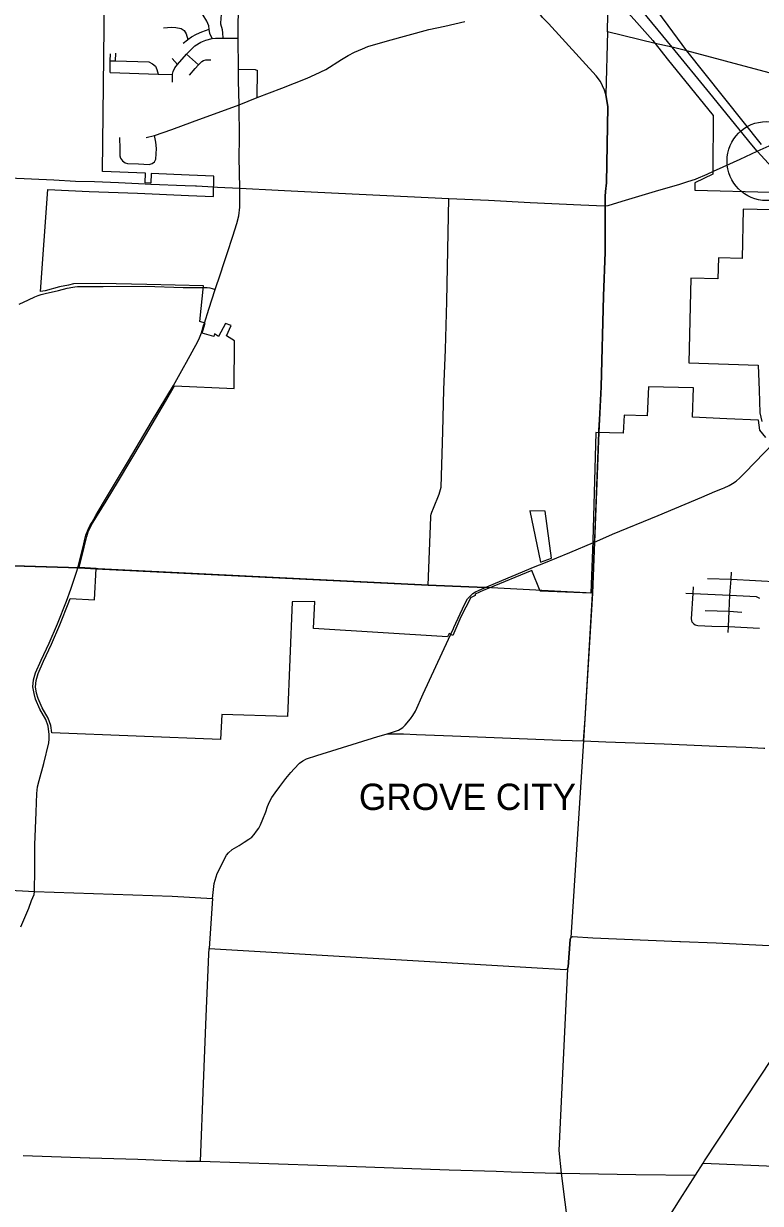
# Model space of a CAD drawing. Extents: x 1659811 to 1934326, y 644115 to 934867.
# Drawn here: x 1783780 to 1797773, y 677476 to 699875 of the extents above; entities that cross this region are included whole.
import ezdxf

# ---------------------------------------------------------------- set-up
doc = ezdxf.new("R2010")
doc.units = 0
for name, color, linetype in [('Default', 7, 'Continuous'), ('GM_X_City_Street', 7, 'Continuous'), ('GM_X_Corporation', 7, 'Continuous'), ('GM_X_Corporation_Text', 7, 'Continuous'), ('GM_X_County_Road', 7, 'Continuous'), ('GM_X_Interstate_Route', 7, 'Continuous'), ('GM_X_Township', 7, 'Continuous'), ('GM_X_Township_Road', 7, 'Continuous'), ('GM_X_US_Route', 7, 'Continuous')]:
    doc.layers.add(name, color=color, linetype=linetype)

msp = doc.modelspace()

# ---------------------------------------------------------------- linework, layer by layer
at = {"layer": 'Default'}
msp.add_circle((1797890, 697266), 750, dxfattribs=at)
at = {"layer": 'GM_X_City_Street'}
for points in [[(1787860, 699018), (1787858, 699597), (1787860, 700358), (1787857, 700738), (1787852, 701242), (1787854, 701665), (1787855, 702336), (1787857, 703006), (1787855, 703286)], [(1787568, 699600), (1787565, 699703), (1787558, 699757), (1787529, 699867), (1787526, 699907), (1787530, 699946), (1787540, 700071), (1787544, 700150), (1787537, 700203), (1787516, 700260), (1787490, 700314), (1787410, 700486), (1787371, 700689)], [(1787359, 699591), (1787316, 699688), (1787305, 699768), (1787296, 699835), (1787257, 699924), (1787193, 700037), (1787087, 700199), (1786996, 700308), (1786904, 700363)], [(1794824, 696413), (1794825, 696594), (1794834, 696685), (1794851, 696855), (1794873, 698294), (1794837, 698528), (1794811, 698613), (1794734, 698773), (1794654, 698882), (1793750, 699877), (1793637, 699992), (1793560, 700096), (1793541, 700135), (1793499, 700228), (1793486, 700349)], [(1786436, 699794), (1786590, 699806), (1786672, 699801), (1786772, 699784), (1786828, 699747), (1786867, 699684), (1786902, 699576)], [(1786813, 699503), (1786890, 699568), (1786902, 699576), (1786972, 699621), (1787067, 699672), (1787164, 699720), (1787305, 699768)], [(1787874, 698335), (1788217, 698471), (1788682, 698648), (1789167, 698839), (1789320, 698907), (1789523, 699005), (1789815, 699194), (1789942, 699267), (1790064, 699333), (1790216, 699398), (1790319, 699438), (1790694, 699548), (1791479, 699763), (1791782, 699829), (1792162, 699917)], [(1786606, 698762), (1786608, 698906), (1786608, 698916), (1786623, 698964), (1786650, 699034), (1786706, 699100), (1786875, 699296), (1786878, 699299), (1787035, 699454), (1787143, 699521), (1787241, 699558), (1787359, 699591), (1787427, 699599), (1787568, 699600), (1787858, 699597)], [(1785525, 699166), (1785529, 699315)], [(1785424, 698946), (1785425, 699168), (1785432, 699299)], [(1785425, 699168), (1785525, 699166), (1786160, 699148), (1786228, 699113), (1786284, 699069), (1786311, 699004), (1786334, 698915)], [(1786602, 699211), (1786706, 699100)], [(1786875, 699296), (1787102, 699091)], [(1786932, 698898), (1787036, 699025), (1787102, 699091), (1787164, 699155), (1787197, 699177), (1787241, 699190), (1787265, 699190), (1787333, 699187)], [(1785424, 698946), (1786334, 698915), (1786608, 698906)], [(1787874, 698334), (1787874, 698335), (1787863, 698796), (1787860, 699008), (1787860, 699018)], [(1787860, 699008), (1788180, 699002), (1788221, 698982)], [(1788217, 698471), (1788221, 698982)], [(1786109, 697716), (1786264, 697748), (1786593, 697867), (1786985, 698008), (1787874, 698335)], [(1787878, 697701), (1787874, 698334)], [(1785601, 697716), (1785608, 697498), (1785608, 697405), (1785608, 697365), (1785620, 697318), (1785657, 697268), (1785707, 697231), (1785753, 697219), (1785960, 697210), (1786164, 697200), (1786225, 697219), (1786264, 697254), (1786292, 697299), (1786302, 697505), (1786292, 697627), (1786264, 697748)], [(1787886, 696753), (1787886, 696753), (1787877, 697338), (1787878, 697696), (1787878, 697701)], [(1796541, 696924), (1796553, 696928), (1796764, 697018), (1796881, 697072)], [(1794815, 696413), (1794824, 696413), (1794882, 696423), (1795150, 696503), (1795462, 696597), (1795846, 696710), (1796227, 696823), (1796396, 696877), (1796541, 696924)], [(1787465, 696773), (1787886, 696753)], [(1787581, 695318), (1787644, 695510), (1787755, 695837), (1787831, 696083), (1787865, 696227), (1787884, 696389), (1787886, 696506), (1787886, 696753)], [(1787886, 696753), (1788614, 696715), (1788733, 696708)], [(1788733, 696708), (1789370, 696675), (1791855, 696557), (1792612, 696521), (1793399, 696481), (1794364, 696432), (1794815, 696413)], [(1791515, 690529), (1791520, 690559), (1791534, 690600), (1791565, 690676), (1791675, 690939), (1791710, 691076), (1791741, 692131), (1791760, 692924), (1791791, 693686), (1791820, 694601), (1791855, 696557)], [(1794723, 692465), (1794750, 692977), (1794796, 694700), (1794822, 695537), (1794824, 696413)], [(1787206, 694162), (1787215, 694190), (1787299, 694452), (1787421, 694829), (1787518, 695126), (1787581, 695318)], [(1787268, 694866), (1787316, 694859), (1787360, 694848), (1787421, 694829)], [(1794627, 690096), (1794704, 692111), (1794706, 692149)], [(1794896, 690150), (1794967, 690182), (1795830, 690539), (1796659, 690885), (1796910, 690990), (1797053, 691047)], [(1791461, 689213), (1791511, 690507), (1791515, 690529)], [(1792546, 689167), (1792624, 689200), (1793496, 689565), (1793662, 689634), (1794151, 689836), (1794604, 690023)], [(1785153, 689525), (1789400, 689315)], [(1797159, 688314), (1797165, 688429), (1797177, 688723), (1797191, 689023), (1797219, 689325), (1797223, 689459)], [(1789400, 689315), (1791461, 689213), (1792546, 689167)], [(1796770, 689338), (1797219, 689325), (1798139, 689277)], [(1791954, 688409), (1792155, 688846), (1792210, 688952), (1792312, 689056), (1792364, 689086), (1792418, 689112), (1792546, 689167)], [(1796354, 689062), (1796496, 689056), (1797191, 689023), (1797575, 689007), (1797690, 688999), (1797755, 688969)], [(1796508, 688481), (1796480, 688509), (1796467, 688576), (1796496, 689056), (1796504, 689184)], [(1796725, 688731), (1797177, 688723)], [(1797177, 688723), (1797422, 688704)], [(1796508, 688481), (1796535, 688458), (1796583, 688449), (1796849, 688438), (1797165, 688429), (1797753, 688400)], [(1794416, 686257), (1794442, 686678)], [(1793981, 686274), (1794416, 686257)], [(1794416, 686257), (1794416, 686257), (1794840, 686242)], [(1796257, 682451), (1796936, 682422), (1798693, 682335), (1798738, 682332)]]:
    msp.add_lwpolyline(points, dxfattribs=at)
at = {"layer": 'GM_X_Corporation'}
for points in [[(1797878, 692016), (1797761, 692155), (1797739, 692347), (1797135, 692373), (1796483, 692401), (1796502, 692961), (1795648, 692976), (1795623, 692428), (1795183, 692443), (1795165, 692098), (1794646, 692113), (1794591, 690057), (1794554, 689062), (1793588, 689102), (1793430, 689495), (1792602, 689150), (1792522, 689120), (1792355, 689043), (1792357, 689019), (1792282, 688977), (1792273, 688982), (1792085, 688610), (1791929, 688257), (1791865, 688297), (1791829, 688232), (1789283, 688392), (1789311, 688902), (1788878, 688896), (1788791, 686723), (1787546, 686758), (1787521, 686284), (1784315, 686409), (1784297, 686550), (1784248, 686686), (1784135, 686884), (1784054, 687065), (1784026, 687166), (1784005, 687285), (1784016, 687404), (1784055, 687534), (1784161, 687771), (1784313, 688095), (1784468, 688460), (1784642, 688892), (1784665, 688961), (1785129, 688938), (1785159, 689533), (1784834, 689548), (1784931, 689934), (1784982, 690138), (1785006, 690224), (1785068, 690356), (1785346, 690811), (1785585, 691197), (1786031, 691948), (1786472, 692703), (1786647, 692995), (1787777, 692949), (1787788, 693850), (1787631, 693946), (1787720, 694143), (1787615, 694183), (1787480, 693935), (1787407, 693985), (1787393, 693937), (1787173, 694001), (1787192, 694061), (1787229, 694190), (1787130, 694219), (1787197, 694898), (1786123, 694919), (1785249, 694942), (1784729, 694937), (1784634, 694912), (1784460, 694879), (1784187, 694804), (1784101, 694787), (1784238, 696723), (1785023, 696690), (1785946, 696653), (1786913, 696612), (1787386, 696593), (1787395, 696979), (1786927, 696998), (1786206, 697031), (1786198, 696846), (1786090, 696851), (1786098, 697036), (1785281, 697066), (1785330, 701438)], [(1797796, 697579), (1796374, 699359), (1795561, 700471)], [(1795016, 700366), (1795730, 699557), (1795774, 699500), (1796002, 699205), (1796875, 698131), (1796869, 697090), (1796869, 697014), (1796529, 696855), (1796530, 696713), (1797967, 696678)], [(1798248, 696334), (1797448, 696353), (1797426, 695417), (1796976, 695428), (1796966, 695028), (1796454, 695040), (1796416, 693437), (1797732, 693391), (1797750, 692915), (1797765, 692483), (1797798, 692324)]]:
    msp.add_lwpolyline(points, dxfattribs=at)
msp.add_lwpolyline([(1793596, 689653), (1793803, 689728), (1793686, 690619), (1793395, 690626)], close=True, dxfattribs=at)
at = {"layer": 'GM_X_County_Road'}
for points in [[(1797603, 697403), (1797710, 697452), (1797940, 697557), (1798111, 697632), (1798183, 697665)], [(1796881, 697072), (1797064, 697155), (1797387, 697304), (1797603, 697403)], [(1782535, 694298), (1782550, 695153), (1782591, 696469), (1782608, 696832), (1782612, 696920), (1782619, 696976), (1783507, 696946), (1784356, 696907), (1784769, 696885), (1785129, 696875), (1785584, 696857), (1786091, 696836), (1786195, 696829), (1786848, 696802), (1787044, 696794)], [(1787044, 696794), (1787062, 696793), (1787389, 696777), (1787465, 696773)], [(1783695, 694551), (1783871, 694632), (1783993, 694688), (1784059, 694711), (1784115, 694732), (1784191, 694752), (1784440, 694810), (1784605, 694851), (1784718, 694873), (1784755, 694880), (1784804, 694882), (1784877, 694883), (1785289, 694884), (1786094, 694888), (1786813, 694868), (1787193, 694865), (1787264, 694866), (1787268, 694866)], [(1786873, 693447), (1787091, 693837), (1787119, 693912), (1787157, 694004), (1787206, 694162)], [(1784810, 689542), (1784924, 689998), (1784946, 690089), (1784965, 690163), (1785009, 690269), (1785040, 690341), (1785080, 690412), (1785153, 690538), (1785300, 690784), (1785526, 691165), (1785771, 691576), (1786210, 692313), (1786624, 693006), (1786817, 693347), (1786873, 693447)], [(1794706, 692149), (1794723, 692465)], [(1797053, 691047), (1797086, 691061), (1797177, 691104), (1797245, 691144), (1797314, 691189), (1797381, 691250), (1797479, 691346), (1798037, 691921)], [(1794604, 690023), (1794625, 690031), (1794896, 690150)], [(1794586, 689044), (1794587, 689062), (1794625, 690031), (1794627, 690096)], [(1783994, 684036), (1783992, 684283), (1784016, 684901), (1784030, 685257), (1784047, 685387), (1784078, 685503), (1784164, 685827), (1784260, 686223), (1784265, 686288), (1784269, 686376), (1784248, 686538), (1784203, 686665), (1784090, 686862), (1784007, 687049), (1783978, 687155), (1783954, 687283), (1783967, 687414), (1784008, 687552), (1784116, 687791), (1784268, 688115), (1784422, 688479), (1784595, 688909), (1784677, 689137), (1784792, 689481), (1784810, 689542)], [(1794442, 686678), (1794586, 689044)], [(1790666, 686385), (1790823, 686437), (1790897, 686460), (1790932, 686479), (1790985, 686514), (1791027, 686555), (1791131, 686674), (1791171, 686741), (1791221, 686822), (1791370, 687150), (1791852, 688189), (1791946, 688390), (1791954, 688409)], [(1787370, 683265), (1787401, 683551), (1787456, 683739), (1787636, 684086), (1787674, 684134), (1787739, 684192), (1787871, 684273), (1787970, 684334), (1788058, 684389), (1788112, 684430), (1788161, 684480), (1788205, 684546), (1788246, 684599), (1788279, 684664), (1788324, 684774), (1788380, 684912), (1788414, 685012), (1788449, 685101), (1788493, 685180), (1788559, 685269), (1788649, 685393), (1788760, 685544), (1788858, 685658), (1788920, 685725), (1789020, 685835), (1789083, 685878), (1789153, 685914), (1789348, 685977), (1790506, 686338), (1790666, 686385), (1790747, 686392), (1790825, 686394), (1790996, 686388), (1791243, 686379), (1791923, 686354), (1793981, 686274)], [(1794840, 686242), (1795948, 686200), (1796943, 686156), (1797495, 686135), (1797838, 686120), (1797860, 686120)], [(1773735, 684084), (1773770, 684068), (1773823, 684048), (1774075, 684022), (1774528, 683999), (1776435, 683842), (1776845, 683820), (1777912, 683762), (1778599, 683726), (1779300, 683688), (1780237, 683632), (1781070, 683572), (1781206, 683562), (1782831, 683463), (1783987, 683396)], [(1783987, 683396), (1783995, 683816), (1783994, 684031), (1783994, 684036)], [(1783728, 682725), (1783880, 683080), (1783933, 683226), (1783978, 683340), (1783987, 683396)], [(1783987, 683396), (1786602, 683307), (1787370, 683265)], [(1787370, 683265), (1787303, 682313)], [(1787303, 682313), (1793425, 681955), (1794075, 681916), (1794108, 681930), (1794122, 681965), (1794160, 682486), (1794171, 682523), (1794199, 682540)], [(1794199, 682540), (1794203, 682542), (1794589, 682521), (1796245, 682451), (1796257, 682451)], [(1783773, 678383), (1785029, 678344), (1785034, 678343), (1785035, 678343)], [(1785035, 678343), (1785949, 678314), (1786867, 678280), (1787140, 678276)], [(1787140, 678276), (1790103, 678176), (1791332, 678132), (1791862, 678115), (1792754, 678086), (1793042, 678073), (1793899, 678052)], [(1793899, 678052), (1793990, 678050), (1795408, 678027), (1796540, 678009)], [(1796685, 678237), (1798943, 678144), (1798949, 678144)]]:
    msp.add_lwpolyline(points, dxfattribs=at)
at = {"layer": 'GM_X_Interstate_Route'}
for points in [[(1797609, 697576), (1796813, 698552), (1796095, 699426), (1795445, 700217), (1795043, 700707)], [(1798257, 696886), (1798060, 697077), (1797924, 697218), (1797710, 697452), (1797609, 697576)]]:
    msp.add_lwpolyline(points, dxfattribs=at)
at = {"layer": 'GM_X_Township'}
for points in [[(1794587, 689062), (1792546, 689167), (1791461, 689213), (1784810, 689542), (1784632, 689548), (1783167, 689596), (1782688, 689618), (1780628, 689706), (1776861, 692396), (1776156, 692877), (1775926, 693071), (1769123, 697982), (1765814, 700371), (1762103, 702170)], [(1827950, 691856), (1821149, 693368), (1820279, 693511), (1817907, 694087), (1815708, 694629), (1815087, 694884), (1813506, 695256), (1811163, 695807), (1810869, 695876), (1810570, 695947), (1810511, 695961), (1809948, 696080), (1809281, 696250), (1808653, 696398), (1805040, 697248), (1799916, 698454), (1798676, 698746), (1796374, 699359), (1796095, 699426), (1795774, 699500), (1794871, 699722), (1794886, 700739)], [(1794871, 699722), (1794837, 698528), (1794873, 698294), (1794851, 696855), (1794834, 696685), (1794825, 696594), (1794824, 696413), (1794822, 695537), (1794796, 694700), (1794750, 692977), (1794704, 692111), (1794625, 690031), (1794587, 689062), (1794416, 686257), (1794171, 682523), (1794160, 682486), (1794122, 681965), (1794108, 681930), (1793947, 678482), (1793990, 678050), (1794416, 674693)]]:
    msp.add_lwpolyline(points, dxfattribs=at)
at = {"layer": 'GM_X_Township_Road'}
for points in [[(1783370, 689590), (1784632, 689548), (1784810, 689542), (1784839, 689541)], [(1784839, 689541), (1785153, 689525)], [(1787140, 678276), (1787198, 679744), (1787246, 681024), (1787298, 682207), (1787303, 682313)]]:
    msp.add_lwpolyline(points, dxfattribs=at)
at = {"layer": 'GM_X_US_Route'}
for points in [[(1796714, 678282), (1798777, 681404), (1799372, 682303), (1799509, 682500), (1799535, 682537)], [(1796540, 678009), (1796540, 678009), (1796685, 678237), (1796713, 678282), (1796714, 678282)], [(1794369, 674621), (1794416, 674693), (1795452, 676291), (1796252, 677554), (1796540, 678009)]]:
    msp.add_lwpolyline(points, dxfattribs=at)

# ---------------------------------------------------------------- texts
at = {"layer": 'GM_X_Corporation_Text'}
msp.add_text('GROVE CITY', height=500, rotation=0, dxfattribs=at).set_placement((1790148, 684945))

doc.saveas('drawing.dxf')
